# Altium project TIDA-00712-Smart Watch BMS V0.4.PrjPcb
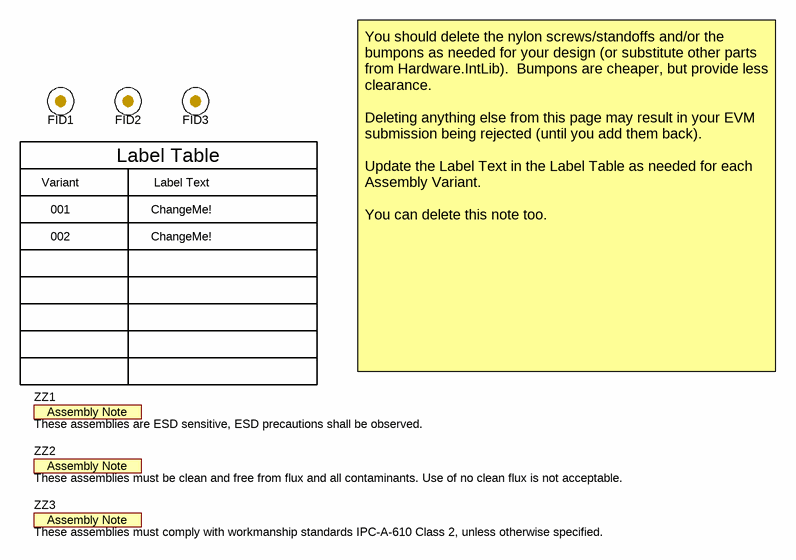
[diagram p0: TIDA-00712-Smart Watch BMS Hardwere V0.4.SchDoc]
CopyrightYear: 2015; EVM_Orderable: N/A; PCB_Layout: Who did the Layout?; PCB_Rev: E1; PRJ_Customer: Public Release; PRJ_Engineer: Enter name of project lead; PRJ_Number: TIDA-xxxxx; PRJ_Title: Change in menu Project|Project Options|Parameters; SCH_Rev: E1; TechSupport: http://www.ti.com/support; TID: ChangeMe!
2 sheets, 79 parts. Net scope: global (net labels, ports and power ports of the same name join across sheets).
Board file: TIDA-00712-Smart Watch BMS PCB V0.4.PcbDoc
Sheets:
  TIDA-00712-Smart Watch BMS Hardwere V0.4.SchDoc
  TIDA-00712-Smart Watch BMS SCH V0.4.SchDoc

## Sheet TIDA-00712-Smart Watch BMS Hardwere V0.4.SchDoc
size 431 x 279 mm; Date: Not shown in title block; ApprovedBy: Not shown in title block; CheckedBy: Not shown in title block; Author: Not shown in title block; CompanyName: Not shown in title block; Engineer: Not shown in title block; Organization: Not shown in title block; Address1: Not shown in title block; Address2: Not shown in title block; Address3: Not shown in title block; Address4: Not shown in title block; DocumentNumber: 1; Revision: Use project parameter SCH_Rev; SheetNumber: 3; SheetTotal: 3; PageSetup: Record=PageOptions¦CenterHorizontal=True¦CenterVertical=True¦PrintScale=1.00¦XCorrection=1.00¦YCorrection=1.00¦PrintKind=0¦BorderSize=5000000¦LeftOffset=0¦BottomOffset=0¦Orientation=2¦PaperLength=1000¦PaperWidth=1000¦Scale=100¦PaperSource=15¦PrintQuality=600¦MediaType=1¦DitherType=10¦PaperKind=Letter¦PrintScaleMode=1

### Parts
FID1  Fiducial  [Fiducial10-20]  (value not drawn)
FID2  Fiducial  [Fiducial10-20]  (value not drawn)
FID3  Fiducial  [Fiducial10-20]  (value not drawn)
ZZ1  These assemblies are ESD sensitive, ESD precautions shall be observed.  [AssemblyNote]  (no BOM)
ZZ2  These assemblies must be clean and free from flux and all contaminants. Use of no clean flux is not acceptable.  [AssemblyNote]  (no BOM)
ZZ3  These assemblies must comply with workmanship standards IPC-A-610 Class 2, unless otherwise specified.  [AssemblyNote]  (no BOM)

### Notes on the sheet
- Variant
- Label Table
- Label Text
- 001
- 002
- ChangeMe!
- You should delete the nylon screws/standoffs and/or the bumpons as needed for your design (or substitute other parts from Hardware.IntLib).  Bumpons are cheaper, but provide less clearance.
  Deleting anything else from this page may result in your EVM submission being rejected (until you add them back).
  Update the Label Text in the Label Table as needed for each Assembly Variant.
  You can delete this note too.

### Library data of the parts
FID1-FID3 = Fiducial: Fiducial mark.  There is nothing to buy or mount.; SymbolCreator: codlsc
ZZ1-ZZ3 = AssemblyNote: SymbolCreator: codlsc

## Sheet TIDA-00712-Smart Watch BMS SCH V0.4.SchDoc: TIDA-00712-Smart Watch BMS SCH V0.4
size 431 x 279 mm; VersionControl_RevNumber: V0.4; Date: Not shown in title block; ApprovedBy: Not shown in title block; CheckedBy: Not shown in title block; Author: Not shown in title block; CompanyName: Not shown in title block; DrawnBy: Phil Yi; Engineer: Not shown in title block; Organization: Not shown in title block; Address1: Not shown in title block; Address2: Not shown in title block; Address3: Not shown in title block; Address4: Not shown in title block; DocumentNumber: 1; Revision: Use project parameter SCH_Rev; SheetNumber: 1; SheetTotal: 1; PageSetup: Record=PageOptions¦CenterHorizontal=True¦CenterVertical=True¦PrintScale=0.98¦XCorrection=1.00¦YCorrection=1.00¦PrintKind=0¦BorderSize=5000000¦LeftOffset=0¦BottomOffset=0¦Orientation=2¦PaperLength=1000¦PaperWidth=1000¦Scale=100¦PaperSource=15¦PrintQuality=-3¦MediaType=1¦DitherType=10¦PrintScaleMode=1¦PaperKind=11 x 17¦PaperIndex=119
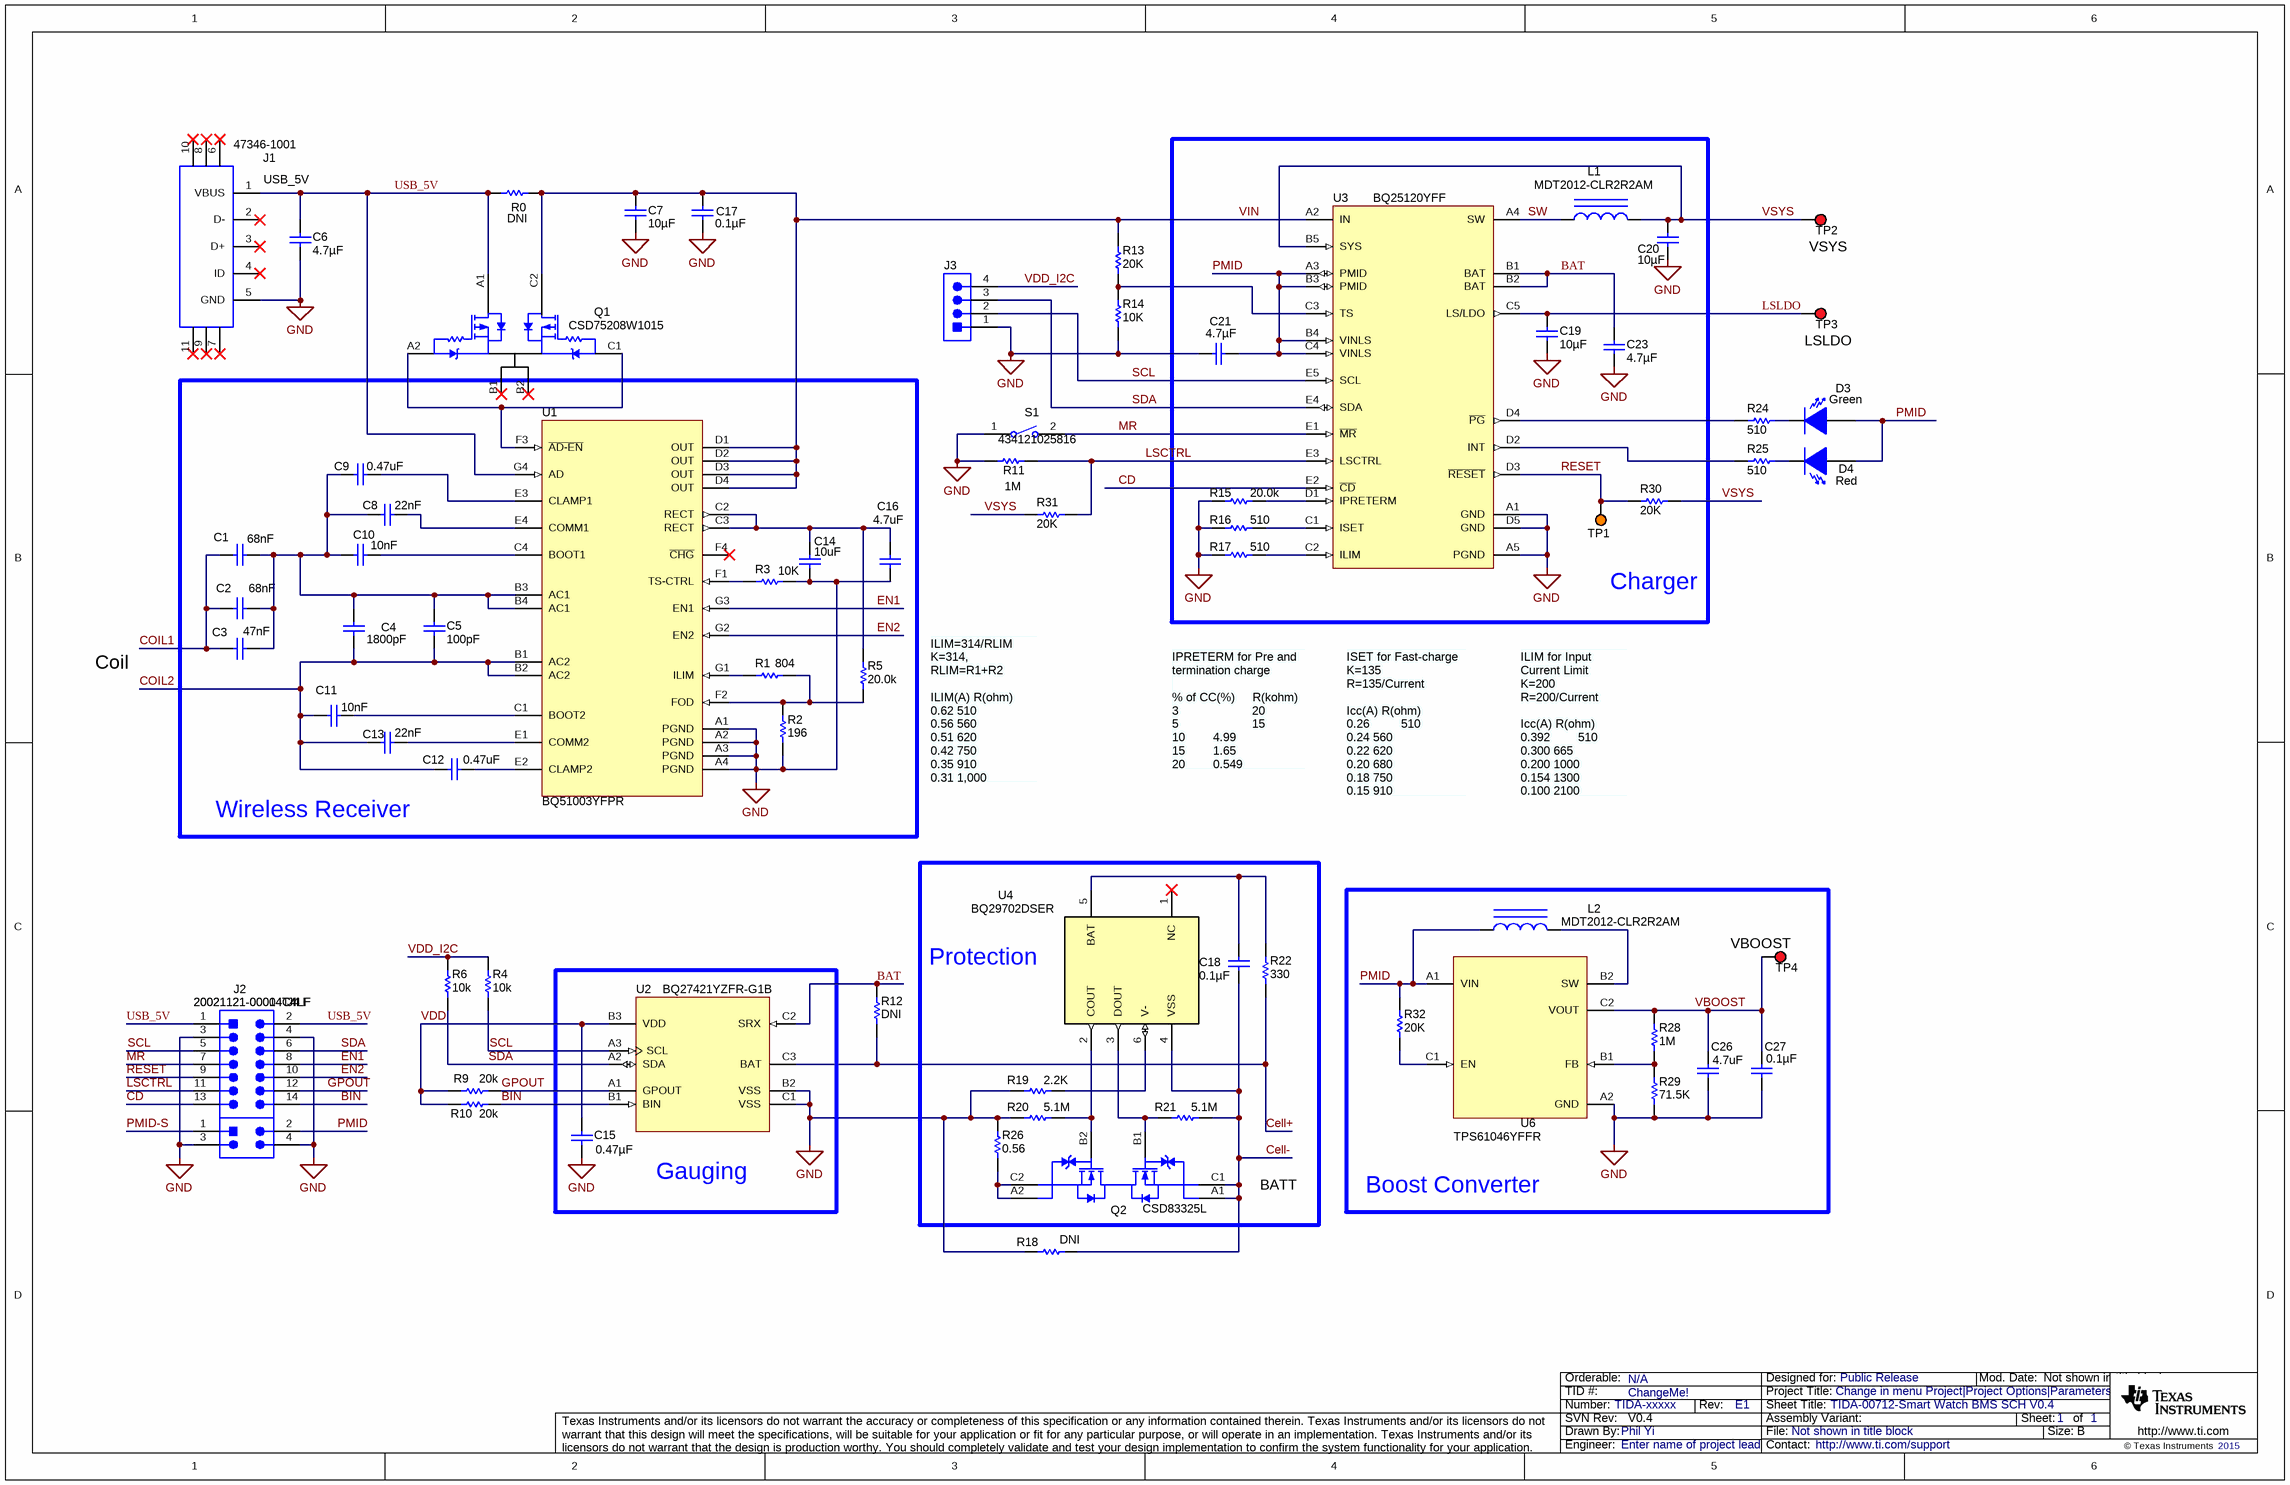
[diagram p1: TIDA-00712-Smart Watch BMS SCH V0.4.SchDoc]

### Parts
C1  ValueDisplayed: 68nF  [0603L]  (hidden comment: GRM188R71E683KA01D)
C2  ValueDisplayed: 68nF  [0603L]  (hidden comment: GRM188R71E683KA01D)
C3  ValueDisplayed: 47nF  [0603L]  (hidden comment: 06033C473JAT2A)
C4  ValueDisplayed: 1800pF  [0402]  (hidden comment: GRM155R71H182KA01D)
C5  ValueDisplayed: 100pF  [0201L]  (hidden comment: GRM033R71E101KA01D)
C6  ValueDisplayed: 4.7µF  [0402]  (hidden comment: GRM155R61C475ME11D)
C7  ValueDisplayed: 10µF  [0402]  (hidden comment: CL05A106MP5NUNC)
C8  ValueDisplayed: 22nF  [0402L]  (hidden comment: GRM155R71E223KA61D)
C9  ValueDisplayed: 0.47uF  [0603L]  (hidden comment: GRM188R71E474KA12D)
C10  ValueDisplayed: 10nF  [0402L]  (hidden comment: GRM155R71E103KA01D)
C11  ValueDisplayed: 10nF  [0402L]  (hidden comment: GRM155R71E103KA01D)
C12  ValueDisplayed: 0.47uF  [0603L]  (hidden comment: GRM188R71E474KA12D)
C13  ValueDisplayed: 22nF  [0402L]  (hidden comment: GRM155R71E223KA61D)
C14  ValueDisplayed: 10uF  [0603L]  (hidden comment: EMK107BBJ106MA-T)
C15  ValueDisplayed: 0.47µF  [0402]  (hidden comment: GRM155R60J474KE19D)
C16  ValueDisplayed: 4.7uF  [0402L]  (hidden comment: GRM188R61C475KAAJ)
C17  ValueDisplayed: 0.1µF  [0402]  (hidden comment: GRM155R61A105KE15D)
C18  ValueDisplayed: 0.1µF  [0402]  (hidden comment: GRM155R61A105KE15D)
C19  ValueDisplayed: 10µF  [0402]  (hidden comment: CL05A106MP5NUNC)
C20  ValueDisplayed: 10µF  [0402]  (hidden comment: CL05A106MP5NUNC)
C21  ValueDisplayed: 4.7µF  [0402]  (hidden comment: GRM155R61C475ME11D)
C23  ValueDisplayed: 4.7µF  [0402]  (hidden comment: GRM155R61A105KE15D)
C26  ValueDisplayed: 4.7uF  [0402L]  (hidden comment: GRM188R61C475KAAJ)
C27  ValueDisplayed: 0.1µF  [0402]  (hidden comment: GRM155R71C104KA88D)
D3  value Green  [LED_LTST-C190]  (hidden comment: LTST-C190GKT)
D4  value Red  [LED_LTST-C190_Red]  (hidden comment: LTST-C190CKT)
J1  47346-1001  [Molex_47346-1001]
J2  20021121-00014T4LF  [FCI_20021121-00014x4]
J3  (no value)  [CONN_22-05-3041]
J4  20021121-00004C4LF  [FCI_20021121-00004C4LF]
L1  MDT2012-CLR2R2AM  [MDT2012-CLR]
L2  MDT2012-CLR2R2AM  [MDT2012-CLR]
Q1  CSD75208W1015  [YZC0006ABBB]
Q2  CSD83325L  [YJE0006A]
R0  ValueDisplayed: DNI  [0402]  (hidden comment: CRCW04024K99FKED)
R1  ValueDisplayed: 804  [0201M]  (hidden comment: CRCW0201845RFKED)
R2  ValueDisplayed: 196  [0201M]  (hidden comment: CRCW0201196RFKED)
R3  ValueDisplayed: 10K  [0201M]  (hidden comment: MCR006YRTF1002)
R4  ValueDisplayed: 10k  [0201M]  (hidden comment: CRCW020120K0FKED)
R5  ValueDisplayed: 20.0k  [0201M]  (hidden comment: CRCW020120K0FKED)
R6  ValueDisplayed: 10k  [0201M]  (hidden comment: CRCW020120K0FKED)
R9  ValueDisplayed: 20k  [0201M]  (hidden comment: CRCW020120K0FKED)
R10  ValueDisplayed: 20k  [0201M]  (hidden comment: CRCW020120K0FKED)
R11  ValueDisplayed: 1M  [0201M]  (hidden comment: CRCW020120K0FKED)
R12  ValueDisplayed: DNI  [0402]  (hidden comment: CRCW04024K99FKED)
R13  ValueDisplayed: 20K  [0201M]  (hidden comment: CRCW020120K0FKED)
R14  ValueDisplayed: 10K  [0201M]  (hidden comment: CRCW020120K0FKED)
R15  ValueDisplayed: 20.0k  [0201M]  (hidden comment: CRCW020120K0FKED)
R16  ValueDisplayed: 510  [0201M]  (hidden comment: CRCW020120K0FKED)
R17  ValueDisplayed: 510  [0201M]  (hidden comment: CRCW020120K0FKED)
R18  ValueDisplayed: DNI  [0402]  (hidden comment: CRCW04024K99FKED)
R19  ValueDisplayed: 2.2K  [0201M]  (hidden comment: CRCW020120K0FKED)
R20  ValueDisplayed: 5.1M  [0201M]  (hidden comment: CRCW020120K0FKED)
R21  ValueDisplayed: 5.1M  [0201M]  (hidden comment: CRCW020120K0FKED)
R22  ValueDisplayed: 330  [0201M]  (hidden comment: CRCW020120K0FKED)
R24  ValueDisplayed: 510  [0201M]  (hidden comment: CRCW020120K0FKED)
R25  ValueDisplayed: 510  [0201M]  (hidden comment: CRCW020120K0FKED)
R26  ValueDisplayed: 0.56  [0201M]  (hidden comment: ERJ-1GEJ1R2C)
R28  ValueDisplayed: 1M  [0201M]  (hidden comment: CRCW020120K0FKED)
R29  ValueDisplayed: 71.5K  [0201M]  (hidden comment: CRCW020120K0FKED)
R30  ValueDisplayed: 20K  [0201M]  (hidden comment: CRCW020120K0FKED)
R31  ValueDisplayed: 20K  [0201M]  (hidden comment: CRCW020120K0FKED)
R32  ValueDisplayed: 20K  [0201M]  (hidden comment: CRCW020120K0FKED)
S1  434121025816  [SW_434121025816]
TP1  5003  [Keystone5003]  (value not drawn)
TP2  5005  [Keystone5005]  (value not drawn)
TP3  5005  [Keystone5005]  (value not drawn)
TP4  5005  [Keystone5005]  (value not drawn)
U1  BQ51003YFPR  [YFP0028APAL]
U2  BQ27421YZFR-G1B  [YZF0009AKAL]
U3  BQ25120YFF  [YFF0025AWAW]
U4  BQ29702DSER  [DSE0006A]
U6  TPS61046YFFR  [YFF0006AAAA]

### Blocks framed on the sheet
Charger: C19-C21 C23 L1 R15-R17 R30 TP1 U3
Wireless Receiver: C1-C5 C8-C14 C16 R1-R3 R5 U1
Protection: C18 Q2 R19-R22 R26 U4
Boost Converter: C26 C27 L2 R28 R29 R32 TP4 U6
Gauging: C15 U2

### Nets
GND: C6.2 C7.2 C14.1 C15.2 C16.2 C17.2 C19.2 C20.2 C21.1 C23.2 C26.2 C27.2 J1.5(GND) J2.3 J2.4 J3.1 J4.3 J4.4 R2.1 R3.1 R11.1 R14.1 R15.1 R16.1 R17.1 R18.1 R19.1 R20.1 R26.2 R29.1 S1.1 U1.A1(PGND) U1.A2(PGND) U1.A3(PGND) U1.A4(PGND) U2.B2(VSS) U2.C1(VSS) U3.A1(GND) U3.A5(PGND) U3.D5(GND) U6.A2(GND)
BAT: C23.1 R12.1 U2.C2(SRX) U3.B1(BAT) U3.B2(BAT)
BIN: J2.14 R10.2 U2.B1(BIN)
CD: J2.13 U3.E2(~{CD})
Cell+: R12.2 R22.1 U2.C3(BAT)
Cell-: C18.2 Q2.A1(S1) Q2.C1(S1) R18.2 R21.2 U4.4(VSS)
COIL1: C1.2 C2.2 C3.2
COIL2: C4.2 C5.1 C11.2 C12.2 C13.2 U1.B1(AC2) U1.B2(AC2)
EN1: J2.8 U1.G3(EN1)
EN2: J2.10 U1.G2(EN2)
GPOUT: J2.12 R9.2 U2.A1(GPOUT)
LSCTRL: J2.11 R11.2 R31.2 U3.E3(LSCTRL)
LSLDO: C19.1 TP3.1 U3.C5(LS/LDO)
MR: J2.7 S1.2 U3.E1(~{MR})
PMID: C21.2 D3.1(A) D4.1(A) J4.2 L2.1 R32.1 U3.A3(PMID) U3.B3(PMID) U3.B4(VINLS) U3.C4(VINLS) U6.A1(VIN)
PMID-S: J4.1
RESET: J2.9 R30.2 TP1.1 U3.D3(~{RESET})
SCL: J2.5 J3.2 R4.2 U2.A3(SCL) U3.E5(SCL)
SDA: J2.6 J3.3 R6.2 U2.A2(SDA) U3.E4(SDA)
SW: L1.1 U3.A4(SW)
USB_5V: C6.1 J1.1(VBUS) J2.1 J2.2 Q1.A1(D2) R0.1 U1.G4(AD)
VBOOST: C26.1 C27.1 R28.2 TP4.1 U6.C2(VOUT)
VDD: C15.1 R9.1 R10.1 U2.B3(VDD)
VDD_I2C: J3.4 R4.1 R6.1
VIN: C7.1 C17.1 Q1.C2(D1) R0.2 R13.2 U1.D1(OUT) U1.D2(OUT) U1.D3(OUT) U1.D4(OUT) U3.A2(IN)
VSYS: C20.1 L1.2 R30.1 R31.1 TP2.1 U3.B5(SYS)
NetC1_1: C1.1 C2.1 C3.1 C4.1 C5.2 C8.2 C9.2 C10.2 U1.B3(AC1) U1.B4(AC1)
NetC8_1: C8.1 U1.E4(COMM1)
NetC9_1: C9.1 U1.E3(CLAMP1)
NetC10_1: C10.1 U1.C4(BOOT1)
NetC11_1: C11.1 U1.C1(BOOT2)
NetC12_1: C12.1 U1.E2(CLAMP2)
NetC13_1: C13.1 U1.E1(COMM2)
NetC14_2: C14.2 C16.1 R5.1 U1.C2(RECT) U1.C3(RECT)
NetC18_1: C18.1 R22.2 U4.5(BAT)
NetD3_2: D3.2(K) R24.2
NetD4_2: D4.2(K) R25.2
NetL2_2: L2.2 U6.B2(SW)
NetQ1_A2: Q1.A2(G2) Q1.C1(G1) U1.F3(~{AD-EN})
NetQ2_A2: Q2.A2(S2) Q2.C2(S2) R26.1
NetQ2_B1: Q2.B1(G1) R21.1 U4.3(DOUT)
NetQ2_B2: Q2.B2(G2) R20.2 U4.2(COUT)
NetR1_1: R1.1 U1.G1(ILIM)
NetR1_2: R1.2 R2.2 R5.2 U1.F2(FOD)
NetR3_2: R3.2 U1.F1(TS-CTRL)
NetR13_1: R13.1 R14.2 U3.C3(TS)
NetR15_2: R15.2 U3.D1(IPRETERM)
NetR16_2: R16.2 U3.C1(ISET)
NetR17_2: R17.2 U3.C2(ILIM)
NetR19_2: R19.2 U4.6(V-)
NetR24_1: R24.1 U3.D4(~{PG})
NetR25_1: R25.1 U3.D2(INT)
NetR28_1: R28.1 R29.2 U6.B1(FB)
NetR32_2: R32.2 U6.C1(EN)

Not connected (* = marked no-connect by the designer): J1 2(D-)* 3(D+)* 4(ID)* 6* 7* 8* 9* 10* 11*; Q1 B1(S)* B2(S)*; U1 F4(~{CHG})*; U4 1(NC)*

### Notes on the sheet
- USB_5V
- (near TP2) VSYS
- (near TP3) LSLDO
- Coil
- IPRETERM for Pre and
  termination charge
  % of CC(%)     R(kohm)
  3                     20
  5                     15
  10	       4.99
  15	       1.65
  20	       0.549
- ILIM=314/RLIM
  K=314,
  RLIM=R1+R2
  ILIM(A)	R(ohm)
  0.62	510
  0.56	560
  0.51	620
  0.42	750
  0.35	910
  0.31	1,000
- ISET for Fast-charge
  K=135
  R=135/Current
  Icc(A)	R(ohm)
  0.26         510
  0.24	560
  0.22	620
  0.20	680
  0.18	750
  0.15	910
  0.12	1100
- ILIM for Input
  Current Limit
  K=200
  R=200/Current
  Icc(A)	R(ohm)
  0.392        510
  0.300	665
  0.200	1000
  0.154	1300
  0.100	2100
  0.050	3920
- (near TP4) VBOOST
- BATT

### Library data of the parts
C1 C2 = GRM188R71E683KA01D: CAP, CERM, 0.068uF, 25V, +/-10%, X7R, 0603; Manufacturer: MuRata; Polarized: N; CompType: Capacitor; U/M: EA; Cap_F: 0.000000068; Tolerance_%: 10; Value1: Unknown; VDC_V: 25; TaMin_C: -55; TaMax_C: 125; Cap_Case: 0603
C3 = 06033C473JAT2A: CAP, CERM, 0.047uF, 25V, +/-5%, X7R, 0603; Manufacturer: AVX; Polarized: N; CompType: Capacitor; U/M: EA; Cap_F: 0.000000047; Tolerance_%: 5; ESR_Ohm: 0.052; Value1: 0.052 ohm; VDC_V: 25; TaMin_C: -55; TaMax_C: 125; Cap_Case: 0603
C4 = GRM155R71H182KA01D: CAP, CERM, 1800 pF, 50 V, +/- 10%, X7R, 0402; Manufacturer: MuRata; Polarized: N; CompType: Capacitor; Value: 1800pF; U/M: EA; Cap_F: 0.0000000018; Tolerance_%: 10; Value1: Unknown; VDC_V: 50; Value2: 50V; TaMin_C: -55; TaMax_C: 125
C5 = GRM033R71E101KA01D: CAP, CERM, 100pF, 25V, +/-10%, X7R, 0201; Manufacturer: MuRata; Polarized: N; CompType: Capacitor; U/M: EA; Cap_F: 0.0000000001; Tolerance_%: 10; Value1: Unknown; VDC_V: 25; TaMin_C: -55; TaMax_C: 125; Cap_Case: 0201
C6 C21 = GRM155R61C475ME11D: CAP, CERM, 4.7 µF, 16 V, +/- 20%, X5R, 0402; Manufacturer: MuRata; Polarized: N; CompType: Capacitor; Value: 4.7uF; U/M: EA; Cap_F: 0.0000047; Tolerance_%: 20; Value1: Unknown; VDC_V: 16; Value2: 16V; TaMin_C: -55; TaMax_C: 85
C7 C19 C20 = CL05A106MP5NUNC: CAP, CERM, 10 µF, 10 V, +/- 20%, X5R, 0402; Manufacturer: Samsung Electro-Mechanics; Polarized: N; CompType: Capacitor; Value: 10uF; U/M: EA; Cap_F: 0.00001; Tolerance_%: 20; Value1: Unknown; VDC_V: 10; Value2: 10V; TaMin_C: -55; TaMax_C: 85
C8 C13 = GRM155R71E223KA61D: CAP, CERM, 0.022uF, 25V, +/-10%, X7R, 0402; Manufacturer: MuRata; Polarized: N; CompType: Capacitor; U/M: EA; Cap_F: 0.000000022; Tolerance_%: 10; Value1: Unknown; VDC_V: 25; TaMin_C: -55; TaMax_C: 125; Cap_Case: 0402
C9 C12 = GRM188R71E474KA12D: CAP, CERM, 0.47uF, 25V, +/-10%, X7R, 0603; Manufacturer: MuRata; Polarized: N; CompType: Capacitor; U/M: EA; Cap_F: 0.00000047; Tolerance_%: 10; Value1: Unknown; VDC_V: 25; TaMin_C: -55; TaMax_C: 125; Cap_Case: 0603
C10 C11 = GRM155R71E103KA01D: CAP, CERM, 0.01uF, 25V, +/-10%, X7R, 0402; Manufacturer: MuRata; Polarized: N; CompType: Capacitor; U/M: EA; Cap_F: 0.00000001; Tolerance_%: 10; Value1: Unknown; VDC_V: 25; TaMin_C: -55; TaMax_C: 125; Cap_Case: 0402
C14 = EMK107BBJ106MA-T: CAP, CERM, 10uF, 16V, +/-20%, X5R, 0603; Manufacturer: Taiyo Yuden; Polarized: N; CompType: Capacitor; U/M: EA; Cap_F: 0.00001; Tolerance_%: 20; Value1: Unknown; VDC_V: 16; TaMin_C: -55; TaMax_C: 85; Cap_Case: 0603
C15 = GRM155R60J474KE19D: CAP, CERM, 0.47 µF, 6.3 V, +/- 10%, X5R, 0402; Manufacturer: MuRata; Polarized: N; CompType: Capacitor; Value: 0.47uF; U/M: EA; Cap_F: 0.00000047; Tolerance_%: 10; Value1: Unknown; VDC_V: 6.3; Value2: 6.3V; TaMin_C: -55; TaMax_C: 85
C16 C26 = GRM188R61C475KAAJ: CAP, CERM, 4.7uF, 16V, +/-10%, X5R, 0603; Manufacturer: MuRata; Polarized: N; CompType: Capacitor; U/M: EA; Cap_F: 0.0000047; Tolerance_%: 10; Value1: Unknown; VDC_V: 16; TaMin_C: -55; TaMax_C: 85; Cap_Case: 0603
C17 C23 = GRM155R61A105KE15D: CAP, CERM, 1 µF, 10 V, +/- 10%, X5R, 0402; Manufacturer: MuRata; Polarized: N; CompType: Capacitor; Value: 1uF; U/M: EA; Cap_F: 0.000001; Tolerance_%: 10; Value1: Unknown; Value2: 10V; TaMin_C: -55; TaMax_C: 85
C18 = GRM155R61A105KE15D: CAP, CERM, 0.1µF, 10 V, +/- 10%, X5R, 0402; Manufacturer: MuRata; Polarized: N; CompType: Capacitor; Value: 1uF; U/M: EA; Cap_F: 0.000001; Tolerance_%: 10; Value1: Unknown; Value2: 10V; TaMin_C: -55; TaMax_C: 85
C27 = GRM155R71C104KA88D: CAP, CERM, 0.1 µF, 16 V, +/- 10%, X7R, 0402; Manufacturer: MuRata; Polarized: N; CompType: Capacitor; Value: 0.1uF; U/M: EA; Cap_F: 0.0000001; Tolerance_%: 10; Value1: Unknown; VDC_V: 16; Value2: 16V; TaMin_C: -55; TaMax_C: 125
D3 = LTST-C190GKT: LED, Green, SMD; Manufacturer: Lite-On; Vf_V: 2.1; Value2: 2.1V; Io_A: 0.02; Power_TotalModule: 0.1; Value1: 0.1W; U/M: EA
D4 = LTST-C190CKT: LED, Red, SMD; Manufacturer: Lite-On; Vf_V: 2; Value2: 2V; Io_A: 0.02; Tjmax_C: 85; Power_TotalModule: 0.0625; Value1: 0.0625W; U/M: EA
J1 = 47346-1001: Receptacle, Micro-USB Type B, 0.65 mm, 5x1, R/A, Bottom Mount SMT; Manufacturer: Molex; SymbolCreator: a0411947; U/M: EA
J2 = 20021121-00014T4LF: Header, 1.27 mm, 7x2, Au, SMT; Manufacturer: FCI; SymbolCreator: a0412235; U/M: EA
J3 = 22-05-3041: Header (friction lock), 100mil, 4x1, R/A, TH; Manufacturer: Molex; SymbolCreator: a0412235; U/M: EA
J4 = 20021121-00004C4LF: Header, 50mil, 2x2, Tin, SMD; Manufacturer: FCI; SymbolCreator: a0412235; U/M: EA
L1 L2 = MDT2012-CLR2R2AM: Inductor, Multilayer, 2.2 µH, 1.35 A, 0.23 ohm, SMD; Manufacturer: Toko; Value: 2.2uH; Ind_H: 2.2E-6; ValueDisplayed: 2.2µH; Imax_A: 1.35; Irms: 1.35A @ 40C rise; DCR_ohm: 0.23; Value2: 1.35A
Q1 = CSD75208W1015: MOSFET, P-CH, -20 V, -1.6 A,; Manufacturer: Texas Instruments; Alternate Manufacturer: None; SymbolCreator: Altium; U/M: EA; ChType: P; Value: -20V; Value1: 0.09 ohm; Rdson45_ohm: 0.09; Value2: 1.9 nC; QgTyp_nC: 1.9; Vgs_V: -6
Q2 = CSD83325L: MOSFET, N-CH,  V,  A,; Manufacturer: Texas Instruments; Alternate Manufacturer: None; SymbolCreator: Altium; U/M: EA; ChType: N; Value1: ? ohm; Value2: 8.4 nC; QgTyp_nC: 8.4; Vgs_V: 10
R0 = CRCW04024K99FKED: RES, 0 Ohm 1%, 0.063 W, 0402; Manufacturer: Vishay-Dale; CompType: Resistor; Value: 4.99k; Res_ohm: 4990; Value_Code: 4k99; Tolerance_%: 1; Power_W: 0.063; Value2: 0.063W; VDC_V: 50; TempCo: 100 ppm/C; EIA_Code: E96; U/M: EA
R1 = CRCW0201845RFKED: RES, 805, 1%, 0.05 W, 0201; Manufacturer: Vishay-Dale; CompType: Resistor; Value: 845; Value_Code: 845R; Tolerance_%: 1; Power_W: 0.05; Value2: 0.05W; VDC_V: 30; TempCo: 100 ppm/C; EIA_Code: E96; U/M: EA
R2 = CRCW0201196RFKED: RES, 196, 1%, 0.05 W, 0201; Manufacturer: Vishay-Dale; CompType: Resistor; Value: 196; Value_Code: 196R; Tolerance_%: 1; Power_W: 0.05; Value2: 0.05W; VDC_V: 30; TempCo: 100 ppm/C; EIA_Code: E96; U/M: EA
R3 = MCR006YRTF1002: RES, 10.0 k, 1%, 0.05 W, 0201; Manufacturer: Rohm; CompType: Resistor; Res_ohm: 10000; Value: 10.0k; Value_Code: 10k0; Tolerance_%: 1; Power_W: 0.05; Value2: 0.05W; VDC_V: 25; TempCo: 250 ppm/C; EIA_Code: E96; U/M: EA
R4-R6 R9-R11 R13-R17 R24 R25 R30-R32 = CRCW020120K0FKED: RES, 20.0 k, 1%, 0.05 W, 0201; Manufacturer: Vishay-Dale; CompType: Resistor; Value: 20.0k; Res_ohm: 20000; Value_Code: 20k0; Tolerance_%: 1; Power_W: 0.05; Value2: 0.05W; VDC_V: 30; TempCo: 100 ppm/C; EIA_Code: E96; U/M: EA
R12 R18 = CRCW04024K99FKED: RES, 0 Ohm, 1%, 0.063 W, 0402; Manufacturer: Vishay-Dale; CompType: Resistor; Value: 4.99k; Res_ohm: 4990; Value_Code: 4k99; Tolerance_%: 1; Power_W: 0.063; Value2: 0.063W; VDC_V: 50; TempCo: 100 ppm/C; EIA_Code: E96; U/M: EA
R19 = CRCW020120K0FKED: RES, 2.2K, 1%, 0.05 W, 0201; Manufacturer: Vishay-Dale; CompType: Resistor; Value: 20.0k; Res_ohm: 20000; Value_Code: 20k0; Tolerance_%: 1; Power_W: 0.05; Value2: 0.05W; VDC_V: 30; TempCo: 100 ppm/C; EIA_Code: E96; U/M: EA
R20 R21 = CRCW020120K0FKED: RES, 5.1M, 1%, 0.05 W, 0201; Manufacturer: Vishay-Dale; CompType: Resistor; Value: 20.0k; Res_ohm: 20000; Value_Code: 20k0; Tolerance_%: 1; Power_W: 0.05; Value2: 0.05W; VDC_V: 30; TempCo: 100 ppm/C; EIA_Code: E96; U/M: EA
R22 = CRCW020120K0FKED: RES, 330, 1%, 0.05 W, 0201; Manufacturer: Vishay-Dale; CompType: Resistor; Value: 20.0k; Res_ohm: 20000; Value_Code: 20k0; Tolerance_%: 1; Power_W: 0.05; Value2: 0.05W; VDC_V: 30; TempCo: 100 ppm/C; EIA_Code: E96; U/M: EA
R26 = ERJ-1GEJ1R2C: RES, 1.2, 5%, 0.05 W, 0201; Manufacturer: Panasonic; CompType: Resistor; Value: 1.2; Value_Code: 1R20; Tolerance_%: 5; Power_W: 0.05; Value2: 0.05W; VDC_V: 15; TempCo: 600 ppm/C; EIA_Code: E24; U/M: EA
R28 = CRCW020120K0FKED: RES, 1M, 1%, 0.05 W, 0201; Manufacturer: Vishay-Dale; CompType: Resistor; Value: 20.0k; Res_ohm: 20000; Value_Code: 20k0; Tolerance_%: 1; Power_W: 0.05; Value2: 0.05W; VDC_V: 30; TempCo: 100 ppm/C; EIA_Code: E96; U/M: EA
R29 = CRCW020120K0FKED: RES, 71.5K 1%, 0.05 W, 0201; Manufacturer: Vishay-Dale; CompType: Resistor; Value: 20.0k; Res_ohm: 20000; Value_Code: 20k0; Tolerance_%: 1; Power_W: 0.05; Value2: 0.05W; VDC_V: 30; TempCo: 100 ppm/C; EIA_Code: E96; U/M: EA
S1 = 434121025816: Switch, Tactile, SPST, 12 V, SMD; Manufacturer: Wurth Elektronik; SymbolCreator: a0799628; VDC_V: 12; SwitchFunction: Off-On; PositionCount: 1; CurrentRating_mA: 50
TP1 = 5003: Test Point, Miniature, Orange, TH; Manufacturer: Keystone; CompType: Test Point Loop; U/M: EA
TP2-TP4 = 5005: Test Point, Compact, Red, TH; Manufacturer: Keystone; CompType: Test Point Loop; U/M: EA
U1 = BQ51003YFPR: Highly Integrated Wireless Receiver Qi (WPC v1.1) Compliant Power Supply, YFP0028APAL; Alternate PartNumber: BQ51003YFPT; Manufacturer: Texas Instruments; Alternate Manufacturer: None; SymbolCreator: Altium; CompType: IC; U/M: EA
U2 = BQ27421YZFR-G1B: System-Side Impedance Track Fuel Gauge With Integrated Sense Resistor, YZF0009AKAL; Alternate PartNumber: BQ27421YZFT-G1B; Manufacturer: Texas Instruments; Alternate Manufacturer: None; SymbolCreator: Altium; CompType: IC; U/M: EA
U3 = BQ25120YFF: YFF0025AWAW; Manufacturer: Texas Instruments; Alternate Manufacturer: None; SymbolCreator: x0208326; CompType: IC; U/M: EA
U4 = BQ29702DSER: Cost-Effective Voltage and Current Protection Integrated Circuit for Single-Cell Li-Ion/Li-Polymer Batteries, DSE0006A; Alternate PartNumber: BQ29702DSET; Manufacturer: Texas Instruments; Alternate Manufacturer: None; SymbolCreator: a0412235; CompType: IC; U/M: EA
U6 = TPS61046YFFR: 28-V Output Voltage Boost Converter in WCSP Package, YFF0006AAAA; Alternate PartNumber: TPS61046YFFT; Manufacturer: Texas Instruments; SymbolCreator: Altium; CompType: IC; U/M: EA

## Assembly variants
001: not fitted FID1 FID2 FID3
